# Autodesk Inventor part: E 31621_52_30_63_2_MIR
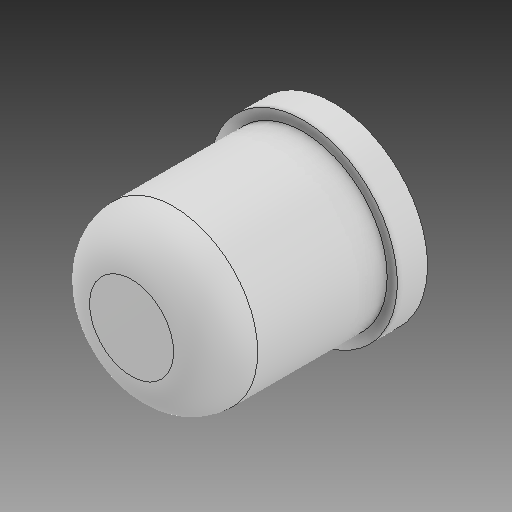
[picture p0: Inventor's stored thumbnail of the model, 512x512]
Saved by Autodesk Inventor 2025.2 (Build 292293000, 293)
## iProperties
Created: 2025-03
Part Number: E 31621_52_30_63_2_MIR
Material: Všeobecné
Description: Pojezd
Document SubType Name: Modeling
Designer: Patrik
Stock Number: Pojezd
Mass: 0.127068 g
Surface Area: 1.42239 cm^2
Volume: 0.127068 cm^3
Density: 1 g/cm^3
Appearance: Výchozí
Author: Patrik
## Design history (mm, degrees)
derived "E 31621_52_30_63_2.ipt"
feature "Těleso1::E 31621_52_30_63_2.ipt" dims "d0" = 10
tag "Prvek štítků1"
node "Těleso1"
